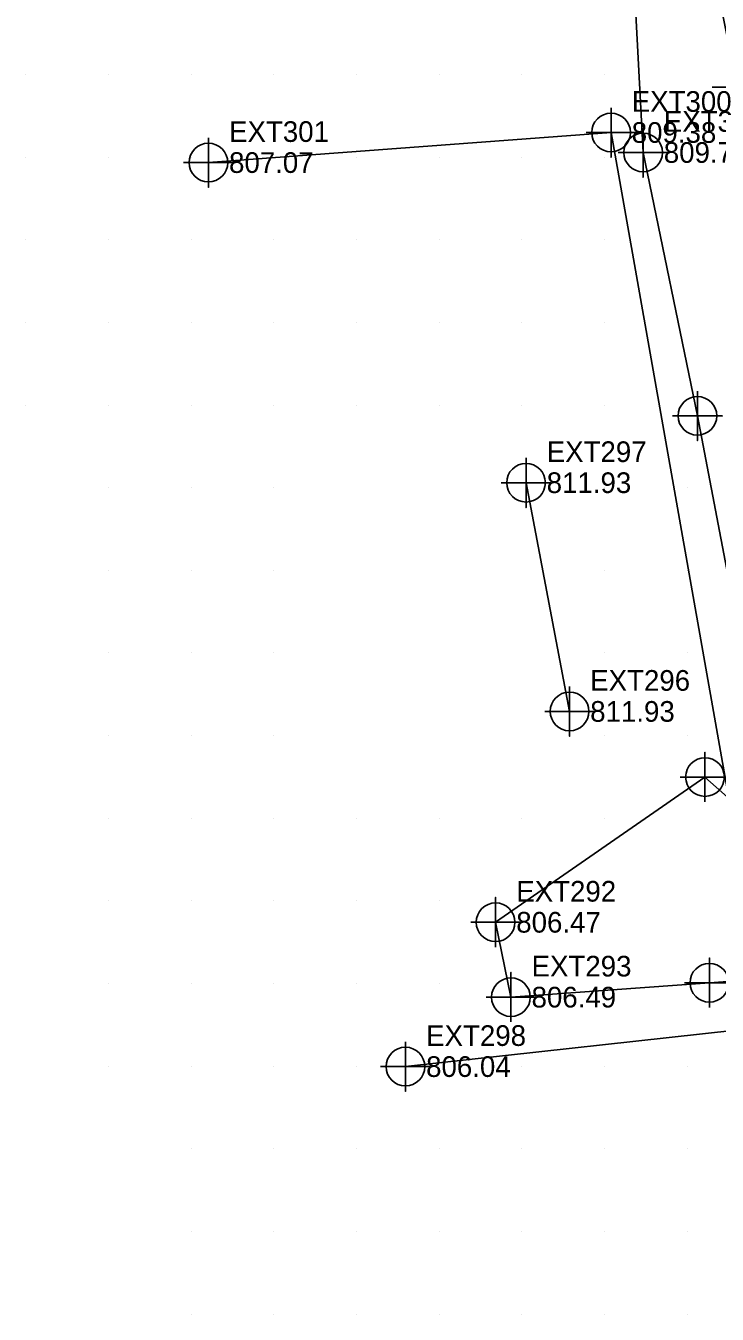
# Model space of a CAD drawing. Extents: x 1762120 to 1766775, y 709485 to 712965.
# Drawn here: x 1763690 to 1763773.6, y 712660 to 712815.9 of the extents above; entities that cross this region are included whole.
import ezdxf

# ---------------------------------------------------------------- set-up
doc = ezdxf.new("R2010")
doc.units = 0
for name, color, linetype in [('Exist Building', 7, 'Continuous'), ('Exist Building Cogo Elevation', 7, 'Continuous'), ('Exist Building Cogo Number', 7, 'Continuous'), ('Exist Building Cogo Point CELL', 7, 'Continuous'), ('Exist DTM Breakline', 7, 'Continuous'), ('Exist DTM Breakline Cogo Elevation', 7, 'Continuous'), ('Exist DTM Breakline Cogo Number', 7, 'Continuous'), ('Exist DTM Breakline Cogo Point CELL', 7, 'Continuous'), ('Exist DTM QL2 LIDAR Elevation Point', 7, 'Continuous'), ('Exist Other Culture Fence Line', 7, 'Continuous'), ('Exist Other Culture Fence Line Cogo Elevation', 7, 'Continuous'), ('Exist Other Culture Fence Line Cogo Number', 7, 'Continuous'), ('Exist Other Culture Fence Line Cogo Point CELL', 7, 'Continuous'), ('Exist Roads Soil', 7, 'Continuous'), ('Exist Roads Soil Cogo Elevation', 7, 'Continuous'), ('Exist Roads Soil Cogo Number', 7, 'Continuous'), ('Exist Roads Soil Cogo Point CELL', 7, 'Continuous')]:
    doc.layers.add(name, color=color, linetype=linetype)

msp = doc.modelspace()

# ---------------------------------------------------------------- linework, layer by layer
at = {"layer": 'Exist Building'}
msp.add_line((1763755.75, 712732.93), (1763750.49, 712760.6), dxfattribs=at)
at = {"layer": 'Exist Building Cogo Point CELL'}
for points in [[(1763750.49, 712763.6), (1763750.49, 712757.6), (1763750.49, 712760.6), (1763753.49, 712760.6), (1763747.49, 712760.6)], [(1763755.75, 712735.93), (1763755.75, 712729.93), (1763755.75, 712732.93), (1763758.75, 712732.93), (1763752.75, 712732.93)]]:
    msp.add_lwpolyline(points, dxfattribs=at)
for centre in [(1763750.49, 712760.6), (1763755.75, 712732.93)]:
    msp.add_circle(centre, 2.34, dxfattribs=at)
at = {"layer": 'Exist DTM Breakline'}
msp.add_lwpolyline([(1763768.87, 712844.44), (1763776.01, 712808.45), (1763782.44, 712776.82), (1763789.54, 712738.64), (1763792.6, 712718.34), (1763784.29, 712719.01), (1763777.9, 712733.6), (1763771.21, 712768.69), (1763764.65, 712800.55), (1763763.2, 712827.98)], dxfattribs=at)
at = {"layer": 'Exist DTM Breakline Cogo Point CELL'}
for points in [[(1763776.01, 712811.45), (1763776.01, 712805.45), (1763776.01, 712808.45), (1763779.01, 712808.45), (1763773.01, 712808.45)], [(1763764.65, 712803.55), (1763764.65, 712797.55), (1763764.65, 712800.55), (1763767.65, 712800.55), (1763761.65, 712800.55)], [(1763771.21, 712771.69), (1763771.21, 712765.69), (1763771.21, 712768.69), (1763774.21, 712768.69), (1763768.21, 712768.69)]]:
    msp.add_lwpolyline(points, dxfattribs=at)
for centre in [(1763764.65, 712800.55), (1763771.21, 712768.69)]:
    msp.add_circle(centre, 2.34, dxfattribs=at)
at = {"layer": 'Exist DTM QL2 LIDAR Elevation Point'}
for p, q in [((1763690, 712810), (1763690, 712810)), ((1763700, 712810), (1763700, 712810)), ((1763710, 712810), (1763710, 712810)), ((1763720, 712810), (1763720, 712810)), ((1763730, 712810), (1763730, 712810)), ((1763740, 712810), (1763740, 712810)), ((1763750, 712810), (1763750, 712810)), ((1763760, 712810), (1763760, 712810)), ((1763690, 712800), (1763690, 712800)), ((1763700, 712800), (1763700, 712800)), ((1763710, 712800), (1763710, 712800)), ((1763720, 712800), (1763720, 712800)), ((1763730, 712800), (1763730, 712800)), ((1763740, 712800), (1763740, 712800)), ((1763750, 712800), (1763750, 712800)), ((1763760, 712800), (1763760, 712800)), ((1763690, 712790), (1763690, 712790)), ((1763700, 712790), (1763700, 712790)), ((1763710, 712790), (1763710, 712790)), ((1763720, 712790), (1763720, 712790)), ((1763730, 712790), (1763730, 712790)), ((1763740, 712790), (1763740, 712790)), ((1763750, 712790), (1763750, 712790)), ((1763760, 712790), (1763760, 712790)), ((1763690, 712780), (1763690, 712780)), ((1763700, 712780), (1763700, 712780)), ((1763710, 712780), (1763710, 712780)), ((1763720, 712780), (1763720, 712780)), ((1763730, 712780), (1763730, 712780)), ((1763740, 712780), (1763740, 712780)), ((1763750, 712780), (1763750, 712780)), ((1763760, 712780), (1763760, 712780)), ((1763690, 712770), (1763690, 712770)), ((1763700, 712770), (1763700, 712770)), ((1763710, 712770), (1763710, 712770)), ((1763720, 712770), (1763720, 712770)), ((1763730, 712770), (1763730, 712770)), ((1763740, 712770), (1763740, 712770)), ((1763750, 712770), (1763750, 712770)), ((1763760, 712770), (1763760, 712770)), ((1763700, 712760), (1763700, 712760)), ((1763710, 712760), (1763710, 712760)), ((1763720, 712760), (1763720, 712760)), ((1763760, 712760), (1763760, 712760)), ((1763770, 712760), (1763770, 712760)), ((1763700, 712750), (1763700, 712750)), ((1763710, 712750), (1763710, 712750)), ((1763720, 712750), (1763720, 712750)), ((1763760, 712750), (1763760, 712750)), ((1763770, 712750), (1763770, 712750)), ((1763700, 712740), (1763700, 712740)), ((1763710, 712740), (1763710, 712740)), ((1763720, 712740), (1763720, 712740)), ((1763760, 712740), (1763760, 712740)), ((1763770, 712740), (1763770, 712740)), ((1763700, 712730), (1763700, 712730)), ((1763710, 712730), (1763710, 712730)), ((1763720, 712730), (1763720, 712730)), ((1763760, 712730), (1763760, 712730)), ((1763770, 712730), (1763770, 712730)), ((1763700, 712720), (1763700, 712720)), ((1763710, 712720), (1763710, 712720)), ((1763720, 712720), (1763720, 712720)), ((1763730, 712720), (1763730, 712720)), ((1763740, 712720), (1763740, 712720)), ((1763750, 712720), (1763750, 712720)), ((1763760, 712720), (1763760, 712720)), ((1763700, 712710), (1763700, 712710)), ((1763710, 712710), (1763710, 712710)), ((1763720, 712710), (1763720, 712710)), ((1763730, 712710), (1763730, 712710)), ((1763740, 712710), (1763740, 712710)), ((1763700, 712700), (1763700, 712700)), ((1763710, 712700), (1763710, 712700)), ((1763720, 712700), (1763720, 712700)), ((1763730, 712700), (1763730, 712700)), ((1763740, 712700), (1763740, 712700)), ((1763700, 712690), (1763700, 712690)), ((1763710, 712690), (1763710, 712690)), ((1763720, 712690), (1763720, 712690)), ((1763730, 712690), (1763730, 712690)), ((1763740, 712690), (1763740, 712690)), ((1763750, 712690), (1763750, 712690)), ((1763760, 712690), (1763760, 712690)), ((1763770, 712690), (1763770, 712690)), ((1763710, 712680), (1763710, 712680)), ((1763720, 712680), (1763720, 712680)), ((1763730, 712680), (1763730, 712680)), ((1763740, 712680), (1763740, 712680)), ((1763750, 712680), (1763750, 712680)), ((1763760, 712680), (1763760, 712680)), ((1763770, 712680), (1763770, 712680)), ((1763710, 712670), (1763710, 712670)), ((1763720, 712670), (1763720, 712670)), ((1763730, 712670), (1763730, 712670)), ((1763740, 712670), (1763740, 712670)), ((1763750, 712670), (1763750, 712670)), ((1763760, 712670), (1763760, 712670)), ((1763770, 712670), (1763770, 712670)), ((1763710, 712660), (1763710, 712660)), ((1763720, 712660), (1763720, 712660)), ((1763730, 712660), (1763730, 712660)), ((1763740, 712660), (1763740, 712660)), ((1763750, 712660), (1763750, 712660)), ((1763760, 712660), (1763760, 712660)), ((1763770, 712660), (1763770, 712660))]:
    msp.add_line(p, q, dxfattribs=at)
at = {"layer": 'Exist Other Culture Fence Line'}
msp.add_lwpolyline([(1763735.91, 712689.96), (1763779.88, 712694.82), (1763760.77, 712802.97), (1763712.08, 712799.33)], dxfattribs=at)
at = {"layer": 'Exist Other Culture Fence Line Cogo Point CELL'}
for points in [[(1763760.77, 712805.97), (1763760.77, 712799.97), (1763760.77, 712802.97), (1763763.77, 712802.97), (1763757.77, 712802.97)], [(1763712.08, 712802.33), (1763712.08, 712796.33), (1763712.08, 712799.33), (1763715.08, 712799.33), (1763709.08, 712799.33)], [(1763735.91, 712692.96), (1763735.91, 712686.96), (1763735.91, 712689.96), (1763738.91, 712689.96), (1763732.91, 712689.96)]]:
    msp.add_lwpolyline(points, dxfattribs=at)
for centre in [(1763760.77, 712802.97), (1763712.08, 712799.33), (1763735.91, 712689.96)]:
    msp.add_circle(centre, 2.34, dxfattribs=at)
at = {"layer": 'Exist Roads Soil'}
msp.add_lwpolyline([(1763799.03, 712713.36), (1763781.73, 712716.47), (1763772.13, 712724.99), (1763746.81, 712707.42), (1763748.66, 712698.36), (1763772.66, 712700.1), (1763800.87, 712702.16)], dxfattribs=at)
at = {"layer": 'Exist Roads Soil Cogo Point CELL'}
for points in [[(1763772.13, 712721.99), (1763772.13, 712727.99), (1763772.13, 712724.99), (1763775.13, 712724.99), (1763769.13, 712724.99)], [(1763746.81, 712704.42), (1763746.81, 712710.42), (1763746.81, 712707.42), (1763749.81, 712707.42), (1763743.81, 712707.42)], [(1763772.66, 712697.1), (1763772.66, 712703.1), (1763772.66, 712700.1), (1763775.66, 712700.1), (1763769.66, 712700.1)], [(1763748.66, 712695.36), (1763748.66, 712701.36), (1763748.66, 712698.36), (1763751.66, 712698.36), (1763745.66, 712698.36)]]:
    msp.add_lwpolyline(points, dxfattribs=at)
for centre in [(1763772.13, 712724.99), (1763746.81, 712707.42), (1763772.66, 712700.1), (1763748.66, 712698.36)]:
    msp.add_circle(centre, 2.34, dxfattribs=at)

# ---------------------------------------------------------------- texts
at = {"layer": 'Exist Building Cogo Elevation'}
for p in [(1763752.99, 712759.35), (1763758.25, 712731.68)]:
    msp.add_text('811.93', height=2.5, dxfattribs=at).set_placement(p)
at = {"layer": 'Exist Building Cogo Number'}
for s, p in [('EXT297', (1763752.99, 712763.1)), ('EXT296', (1763758.25, 712735.43))]:
    msp.add_text(s, height=2.5, dxfattribs=at).set_placement(p)
at = {"layer": 'Exist DTM Breakline Cogo Elevation'}
msp.add_text('809.70', height=2.5, dxfattribs=at).set_placement((1763767.15, 712799.3))
at = {"layer": 'Exist DTM Breakline Cogo Number'}
msp.add_text('EXT311', height=2.5, dxfattribs=at).set_placement((1763767.15, 712803.05))
at = {"layer": 'Exist Other Culture Fence Line Cogo Elevation'}
for s, p in [('809.38', (1763763.27, 712801.72)), ('807.07', (1763714.58, 712798.08)), ('806.04', (1763738.41, 712688.71))]:
    msp.add_text(s, height=2.5, dxfattribs=at).set_placement(p)
at = {"layer": 'Exist Other Culture Fence Line Cogo Number'}
for s, p in [('EXT300', (1763763.27, 712805.47)), ('EXT301', (1763714.58, 712801.83)), ('EXT298', (1763738.41, 712692.46))]:
    msp.add_text(s, height=2.5, dxfattribs=at).set_placement(p)
at = {"layer": 'Exist Roads Soil Cogo Elevation'}
for s, p in [('806.47', (1763749.31, 712706.17)), ('806.49', (1763751.16, 712697.11))]:
    msp.add_text(s, height=2.5, dxfattribs=at).set_placement(p)
at = {"layer": 'Exist Roads Soil Cogo Number'}
for s, p in [('EXT292', (1763749.31, 712709.92)), ('EXT293', (1763751.16, 712700.86))]:
    msp.add_text(s, height=2.5, dxfattribs=at).set_placement(p)

doc.saveas('drawing.dxf')
